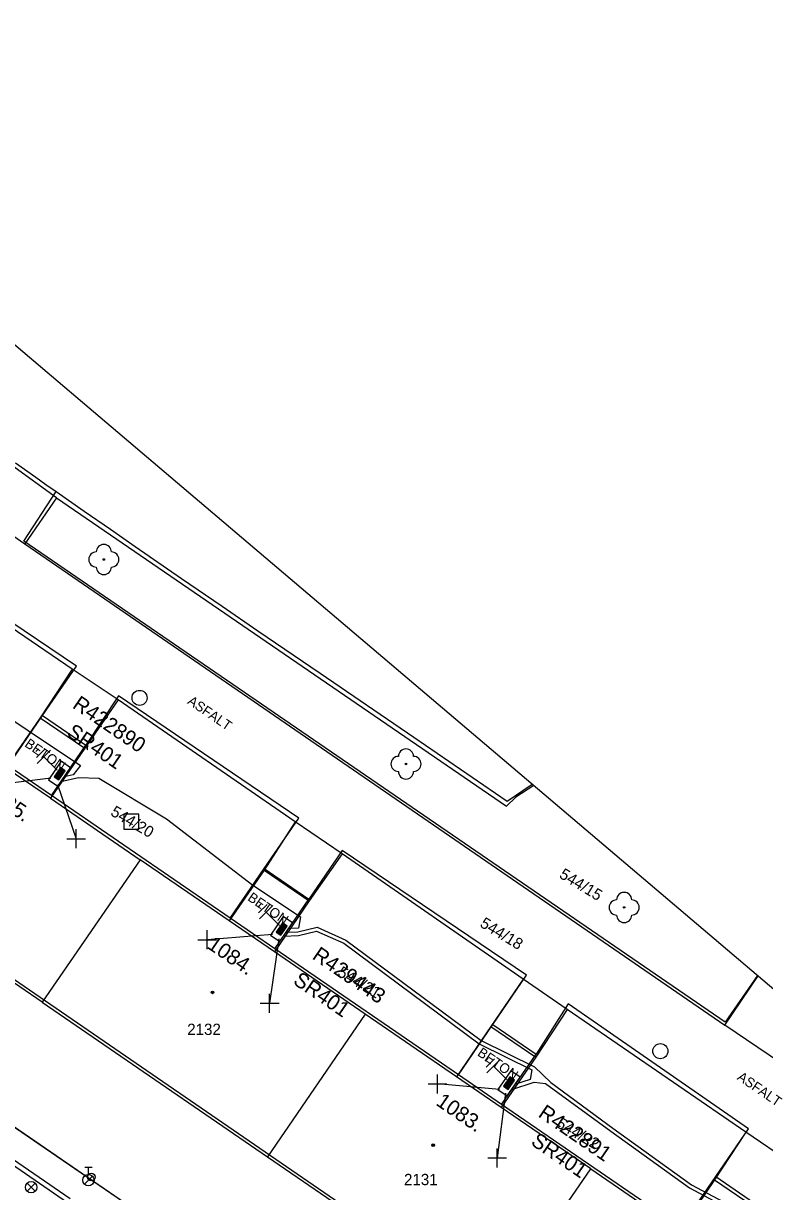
# Model space of a CAD drawing. Extents: x -540150 to -533593, y -1185082 to -1180066.
# Drawn here: x -536371 to -536321.9, y -1184281.4 to -1184203.9 of the extents above; entities that cross this region are included whole.
import ezdxf

# ---------------------------------------------------------------- set-up
doc = ezdxf.new("R2010")
doc.units = 0
for name, color, linetype in [('KN_HRAN_PARCEL', 7, 'Continuous'), ('KN_PARC_Č', 7, 'Continuous'), ('KN_VKP_HRAN_', 7, 'Continuous'), ('rámeček', 7, 'Continuous'), ('Vrstva 1', 7, 'Continuous'), ('Vrstva 10', 7, 'Continuous'), ('Vrstva 11', 7, 'Continuous'), ('Vrstva 14', 7, 'Continuous'), ('Vrstva 15', 7, 'Continuous'), ('Vrstva 22', 7, 'Continuous'), ('Vrstva 26', 7, 'Continuous'), ('Vrstva 27', 7, 'Continuous'), ('Vrstva 28', 7, 'Continuous'), ('Vrstva 29', 7, 'Continuous'), ('Vrstva 30', 7, 'Continuous'), ('Vrstva 33', 7, 'Continuous'), ('Vrstva 34', 7, 'Continuous'), ('Vrstva 39', 7, 'Continuous'), ('Vrstva 40', 7, 'Continuous'), ('Vrstva 47', 7, 'Continuous'), ('Vrstva 5', 7, 'Continuous'), ('Vrstva 59', 7, 'Continuous'), ('Vrstva 8', 7, 'Continuous')]:
    doc.layers.add(name, color=color, linetype=linetype)

# ---------------------------------------------------------------- blocks, each defined once
blk = doc.blocks.new('NN800')
at = {"layer": 'Vrstva 1'}
for points in [[(-0.442, 0.442), (0.442, -0.442)], [(-0.442, -0.442), (0.442, 0.442)]]:
    blk.add_lwpolyline(points, dxfattribs=at)
blk = doc.blocks.new('NN620')
at = {"layer": 'Vrstva 8'}
for points in [[(0.752, 0.004), (-0.748, 0.004)], [(-0.748, 0.004), (-0.748, -0.746)], [(0.752, -0.746), (0.752, 0.004)], [(-0.748, -0.746), (0.752, -0.746)], [(0.368, -0.18), (-0.376, -0.18)], [(-0.376, -0.18), (-0.376, -0.558)], [(-0.376, -0.558), (0.368, -0.558)], [(0.321, -0.227), (-0.329, -0.227)], [(-0.329, -0.227), (-0.329, -0.51)], [(-0.329, -0.51), (0.321, -0.51)], [(0.274, -0.274), (-0.281, -0.274)], [(-0.281, -0.274), (-0.281, -0.463)], [(-0.281, -0.463), (0.274, -0.463)], [(0.227, -0.321), (-0.234, -0.321)], [(-0.234, -0.321), (-0.234, -0.416)], [(-0.234, -0.416), (0.227, -0.416)], [(-0.193, -0.369), (0.185, -0.369)], [(0.227, -0.416), (0.227, -0.321)], [(0.274, -0.463), (0.274, -0.274)], [(0.321, -0.51), (0.321, -0.227)], [(0.368, -0.558), (0.368, -0.18)]]:
    blk.add_lwpolyline(points, dxfattribs=at)
blk = doc.blocks.new('NN810')
at = {"layer": 'Vrstva 14'}
for points in [[(0.004, -0.64), (0.004, -1.89)], [(0.629, -1.89), (-0.621, -1.89)], [(0.388, -2.2), (-0.399, -2.2)], [(0.004, -2.515), (-0.124, -2.515)], [(0.137, -2.515), (0.004, -2.515)]]:
    blk.add_lwpolyline(points, dxfattribs=at)

msp = doc.modelspace()

# ---------------------------------------------------------------- linework, layer by layer
at = {"layer": 'KN_HRAN_PARCEL'}
for p, q in [((-536368.841, -1184235.375), (-536371.841, -1184233.195)), ((-536368.841, -1184235.375), (-536370.941, -1184238.415)), ((-536368.841, -1184235.375), (-536339.001, -1184255.815)), ((-536370.941, -1184238.415), (-536324.521, -1184270.335)), ((-536367.811, -1184246.735), (-536379.651, -1184238.645)), ((-536367.811, -1184246.735), (-536369.931, -1184249.955)), ((-536364.751, -1184248.765), (-536367.811, -1184246.735)), ((-536364.751, -1184248.765), (-536366.971, -1184251.975)), ((-536353.011, -1184256.845), (-536364.751, -1184248.765)), ((-536369.931, -1184249.955), (-536372.211, -1184253.265)), ((-536366.971, -1184251.975), (-536369.251, -1184255.295)), ((-536337.182, -1184254.454), (-536338.391, -1184255.215)), ((-536369.251, -1184255.295), (-536363.311, -1184259.365)), ((-536338.391, -1184255.215), (-536339.001, -1184255.815)), ((-536353.011, -1184256.845), (-536355.071, -1184260.055)), ((-536349.911, -1184258.975), (-536353.011, -1184256.845)), ((-536369.801, -1184268.815), (-536384.621, -1184258.655)), ((-536363.311, -1184259.365), (-536369.801, -1184268.815)), ((-536357.391, -1184263.425), (-536363.311, -1184259.365)), ((-536349.911, -1184258.975), (-536352.081, -1184262.105)), ((-536337.891, -1184267.285), (-536349.911, -1184258.975)), ((-536355.071, -1184260.055), (-536357.391, -1184263.425)), ((-536352.081, -1184262.105), (-536354.391, -1184265.485)), ((-536396.091, -1184262.855), (-536368.121, -1184282.095)), ((-536348.371, -1184269.615), (-536354.391, -1184265.485)), ((-536386.601, -1184266.835), (-536327.371, -1184307.455)), ((-536324.521, -1184270.335), (-536322.318, -1184267.076)), ((-536337.891, -1184267.285), (-536340.041, -1184270.435)), ((-536334.971, -1184269.295), (-536337.891, -1184267.285)), ((-536369.801, -1184268.815), (-536354.851, -1184279.065)), ((-536334.971, -1184269.295), (-536337.061, -1184272.465)), ((-536323.121, -1184277.445), (-536334.971, -1184269.295)), ((-536348.371, -1184269.615), (-536354.851, -1184279.065)), ((-536342.321, -1184273.765), (-536348.371, -1184269.615)), ((-536340.041, -1184270.435), (-536342.321, -1184273.765)), ((-536337.061, -1184272.465), (-536339.351, -1184275.795)), ((-536333.411, -1184279.865), (-536339.351, -1184275.795)), ((-536323.121, -1184277.445), (-536325.201, -1184280.605)), ((-536320.091, -1184279.515), (-536323.121, -1184277.445)), ((-536354.851, -1184279.065), (-536339.901, -1184289.315)), ((-536339.901, -1184289.315), (-536333.411, -1184279.865)), ((-536333.411, -1184279.865), (-536327.481, -1184283.935)), ((-536325.201, -1184280.605), (-536327.481, -1184283.935))]:
    msp.add_line(p, q, dxfattribs=at)
at = {"layer": 'KN_VKP_HRAN_'}
for p, q in [((-536376.141, -1184234.855), (-536370.941, -1184238.415)), ((-536369.931, -1184249.955), (-536366.971, -1184251.975)), ((-536369.251, -1184255.295), (-536372.211, -1184253.265)), ((-536355.071, -1184260.055), (-536352.081, -1184262.105)), ((-536354.391, -1184265.485), (-536357.391, -1184263.425)), ((-536340.041, -1184270.435), (-536337.061, -1184272.465)), ((-536319.161, -1184273.985), (-536324.521, -1184270.335)), ((-536339.351, -1184275.795), (-536342.321, -1184273.765)), ((-536325.201, -1184280.605), (-536322.231, -1184282.635))]:
    msp.add_line(p, q, dxfattribs=at)
at = {"layer": 'rámeček'}
msp.add_lwpolyline([(-536863.363, -1184184.148), (-536677.591, -1183965.383), (-535884.856, -1184638.563), (-536070.628, -1184857.328)], close=True, dxfattribs=at)
at = {"layer": 'Vrstva 10'}
for p, q in [((-536355.498, -1184244.178), (-536351.364, -1184247.004)), ((-536351.364, -1184247.004), (-536345.16, -1184251.241))]:
    msp.add_line(p, q, dxfattribs=at)
for points in [[(-536371.561, -1184233.045), (-536370.223, -1184233.998), (-536369.553, -1184234.473), (-536368.881, -1184234.945), (-536367.02, -1184236.241), (-536365.273, -1184237.453), (-536363.633, -1184238.587)], [(-536363.633, -1184238.587), (-536360.555, -1184240.709), (-536357.859, -1184242.56), (-536355.498, -1184244.178)], [(-536345.16, -1184251.241), (-536342.059, -1184253.361), (-536338.961, -1184255.485)], [(-536338.961, -1184255.485), (-536337.911, -1184254.775), (-536337.295, -1184254.359)]]:
    msp.add_lwpolyline(points, dxfattribs=at)
at = {"layer": 'Vrstva 11'}
for p, q in [((-536371.021, -1184238.235), (-536368.881, -1184234.945)), ((-536367.521, -1184246.535), (-536379.771, -1184238.255)), ((-536324.491, -1184270.145), (-536371.021, -1184238.235)), ((-536369.767, -1184249.809), (-536367.521, -1184246.535)), ((-536364.741, -1184248.495), (-536366.901, -1184251.775)), ((-536352.781, -1184256.605), (-536364.741, -1184248.495)), ((-536372.057, -1184253.148), (-536369.767, -1184249.809)), ((-536369.767, -1184249.809), (-536366.901, -1184251.775)), ((-536369.191, -1184255.114), (-536366.901, -1184251.775)), ((-536355.076, -1184259.951), (-536352.781, -1184256.605)), ((-536349.901, -1184258.765), (-536352.111, -1184261.985)), ((-536337.671, -1184267.035), (-536349.901, -1184258.765)), ((-536357.336, -1184263.246), (-536355.076, -1184259.951)), ((-536355.076, -1184259.951), (-536352.111, -1184261.985)), ((-536354.371, -1184265.28), (-536352.111, -1184261.985)), ((-536367.941, -1184281.865), (-536396.121, -1184262.535)), ((-536387.071, -1184266.585), (-536327.131, -1184307.495)), ((-536339.909, -1184270.298), (-536337.671, -1184267.035)), ((-536322.356, -1184267.044), (-536324.491, -1184270.145)), ((-536334.911, -1184268.925), (-536337.041, -1184272.265)), ((-536322.951, -1184277.215), (-536334.911, -1184268.925)), ((-536342.195, -1184273.631), (-536339.909, -1184270.298)), ((-536339.909, -1184270.298), (-536337.041, -1184272.265)), ((-536339.327, -1184275.598), (-536337.041, -1184272.265)), ((-536325.126, -1184280.386), (-536322.951, -1184277.215)), ((-536327.437, -1184283.755), (-536325.126, -1184280.386)), ((-536325.126, -1184280.386), (-536322.271, -1184282.345))]:
    msp.add_line(p, q, dxfattribs=at)
at = {"layer": 'Vrstva 22'}
for centre in [(-536365.711, -1184239.455), (-536345.671, -1184253.015), (-536331.201, -1184262.535)]:
    msp.add_circle(centre, 0.05, dxfattribs=at)
for centre, start, end in [((-536365.711, -1184238.955), 0, 180), ((-536366.211, -1184239.455), 90, 270), ((-536365.211, -1184239.455), 270, 90), ((-536365.711, -1184239.955), 180, 0), ((-536345.671, -1184252.515), 0, 180), ((-536346.171, -1184253.015), 90, 270), ((-536345.171, -1184253.015), 270, 90), ((-536345.671, -1184253.515), 180, 0), ((-536331.201, -1184262.035), 0, 180), ((-536331.701, -1184262.535), 90, 270), ((-536330.701, -1184262.535), 270, 90), ((-536331.201, -1184263.035), 180, 0)]:
    msp.add_arc(centre, 0.5, start, end, dxfattribs=at)
at = {"layer": 'Vrstva 26'}
msp.add_lwpolyline([(-536364.391, -1184257.345), (-536363.391, -1184257.345), (-536363.391, -1184256.345), (-536364.391, -1184256.345)], close=True, dxfattribs=at)
at = {"layer": 'Vrstva 27'}
for centre in [(-536363.341, -1184248.635), (-536328.801, -1184272.065)]:
    msp.add_circle(centre, 0.5, dxfattribs=at)
at = {"layer": 'Vrstva 28'}
for p, q in [((-536366.981, -1184279.75), (-536366.481, -1184279.75)), ((-536366.731, -1184280.25), (-536366.731, -1184279.75)), ((-536366.989, -1184280.897), (-536366.459, -1184280.367))]:
    msp.add_line(p, q, dxfattribs=at)
for centre, radius in [((-536366.731, -1184280.625), 0.375), ((-536366.531, -1184280.415), 0.25)]:
    msp.add_circle(centre, radius, dxfattribs=at)
at = {"layer": 'Vrstva 33'}
for p, q in [((-536370.796, -1184281.355), (-536370.266, -1184280.825)), ((-536370.796, -1184280.825), (-536370.266, -1184281.355))]:
    msp.add_line(p, q, dxfattribs=at)
msp.add_circle((-536370.531, -1184281.09), 0.375, dxfattribs=at)
at = {"layer": 'Vrstva 39'}
for centre, radius in [((-536358.503, -1184268.166), 0.09), ((-536358.503, -1184268.166), 0.0398), ((-536343.869, -1184278.302), 0.09), ((-536343.869, -1184278.302), 0.0398)]:
    msp.add_circle(centre, radius, dxfattribs=at)
at = {"layer": 'Vrstva 5'}
msp.add_line((-536399.601, -1184248.105), (-536295.161, -1184319.845), dxfattribs=at)
for points in [[(-536288.671, -1184310.345), (-536294.81, -1184306.134), (-536297.708, -1184304.146), (-536309.633, -1184295.967), (-536312.525, -1184293.983), (-536324.581, -1184285.713), (-536327.437, -1184283.755), (-536339.327, -1184275.598), (-536342.195, -1184273.631), (-536354.371, -1184265.28), (-536357.336, -1184263.246), (-536369.191, -1184255.114), (-536372.057, -1184253.148), (-536384.25, -1184244.785), (-536387.023, -1184242.883), (-536393.201, -1184238.645)], [(-536383.63, -1184243.882), (-536383.364, -1184244.075), (-536381.872, -1184243.709), (-536381.221, -1184243.785), (-536367.251, -1184253.115), (-536367.733, -1184253.734), (-536368.342, -1184253.876)], [(-536368.553, -1184254.184), (-536367.401, -1184253.904), (-536366.031, -1184253.965), (-536361.551, -1184256.655), (-536355.831, -1184261.065), (-536352.661, -1184263.155), (-536352.797, -1184263.914), (-536353.439, -1184263.921)], [(-536353.614, -1184264.176), (-536352.841, -1184264.155), (-536351.563, -1184263.846), (-536349.657, -1184264.696), (-536340.685, -1184271.368), (-536337.15, -1184273.115), (-536336.071, -1184274.148), (-536331.947, -1184277.164), (-536326.745, -1184280.929), (-536322.484, -1184283.194), (-536321.889, -1184283.83), (-536310.905, -1184291.519), (-536307.667, -1184293.318), (-536306.774, -1184294.493), (-536301.44, -1184298.102), (-536296.164, -1184301.849), (-536292.71, -1184303.81), (-536288.61, -1184306.862), (-536279.86, -1184312.522), (-536276.264, -1184315.206), (-536273.747, -1184317.246), (-536270.671, -1184318.646), (-536271.035, -1184319.919), (-536273.507, -1184322.601)], [(-536353.789, -1184264.431), (-536352.808, -1184264.404), (-536351.599, -1184264.104), (-536349.785, -1184264.914), (-536340.817, -1184271.582), (-536337.316, -1184273.311), (-536337.433, -1184273.938), (-536338.408, -1184274.259)], [(-536338.642, -1184274.6), (-536337.163, -1184274.112), (-536336.413, -1184274.21), (-536332.095, -1184277.366), (-536326.877, -1184281.141), (-536322.607, -1184283.412), (-536322.782, -1184283.88), (-536323.795, -1184284.568)]]:
    msp.add_lwpolyline(points, dxfattribs=at)
at = {"layer": 'Vrstva 59'}
for points in [[(-536369.229, -1184253.957), (-536372.437, -1184254.352)], [(-536368.784, -1184254.385), (-536367.55, -1184257.973)], [(-536354.515, -1184264.329), (-536358.859, -1184264.675)], [(-536354.104, -1184264.625), (-536354.713, -1184268.888)], [(-536339.472, -1184274.604), (-536343.585, -1184274.242)], [(-536339.077, -1184274.851), (-536339.62, -1184279.146)]]:
    msp.add_lwpolyline(points, dxfattribs=at)

# ---------------------------------------------------------------- block references
at = {"layer": 'Vrstva 15', "rotation": -135}
for p in [(-536368.342, -1184253.876), (-536353.614, -1184264.176), (-536338.531, -1184274.402)]:
    msp.add_blockref('NN810', p, dxfattribs=at)
at = {"layer": 'Vrstva 28'}
for p, rotation in [((-536368.342, -1184253.877), -124.45811942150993), ((-536353.614, -1184264.177), -124.4581195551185), ((-536338.531, -1184274.403), -124.45811942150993)]:
    msp.add_blockref('NN620', p, dxfattribs=dict(at, rotation=rotation))
at = {"layer": 'Vrstva 34'}
for p, rotation in [((-536367.55, -1184257.974), 45), ((-536358.859, -1184264.676), 44.99999995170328), ((-536354.713, -1184268.889), 45), ((-536343.585, -1184274.242), 45.00000009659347), ((-536339.62, -1184279.147), 45)]:
    msp.add_blockref('NN800', p, dxfattribs=dict(at, rotation=rotation))

# ---------------------------------------------------------------- texts
at = {"layer": 'KN_PARC_Č'}
for s, rotation, p in [('544/20', 329.4, (-536365.321, -1184256.385)), ('544/15', 328.5, (-536335.561, -1184260.525)), ('544/18', 328.5, (-536340.821, -1184263.775)), ('544/21', 329.4, (-536350.271, -1184267.035)), ('544/22', 329.4, (-536335.761, -1184277.055))]:
    msp.add_text(s, height=0.75, rotation=rotation, dxfattribs=at).set_placement(p)
for s, p in [('2132', (-536360.181, -1184270.995)), ('2131', (-536345.801, -1184280.955))]:
    msp.add_text(s, height=0.75, dxfattribs=at).set_placement(p)
at = {"layer": 'Vrstva 29'}
for s, p in [('R422890', (-536367.852, -1184249.249)), ('R429443', (-536351.952, -1184265.898)), ('R422891', (-536336.966, -1184276.368))]:
    msp.add_text(s, height=1, rotation=325.542, dxfattribs=at).set_placement(p)
at = {"layer": 'Vrstva 30'}
for p in [(-536368.243, -1184251.105), (-536353.222, -1184267.558), (-536337.454, -1184278.224)]:
    msp.add_text('SR401', height=1, rotation=325.542, dxfattribs=at).set_placement(p)
at = {"layer": 'Vrstva 40'}
for s, rotation, p in [('ASFALT', 325.5579, (-536360.215, -1184248.979)), ('BETON', 325.5527, (-536371.011, -1184251.816)), ('BETON', 325.5527, (-536356.225, -1184262.019)), ('BETON', 325.5527, (-536340.986, -1184272.314)), ('ASFALT', 325.57705, (-536323.756, -1184273.912))]:
    msp.add_text(s, height=0.65, rotation=rotation, dxfattribs=at).set_placement(p)
at = {"layer": 'Vrstva 47'}
for s, p in [('1085.', (-536373.756, -1184255.013)), ('1084.', (-536358.926, -1184265.186)), ('1083.', (-536343.748, -1184275.597))]:
    msp.add_text(s, height=1, rotation=325.5527, dxfattribs=at).set_placement(p)

doc.saveas('drawing.dxf')
